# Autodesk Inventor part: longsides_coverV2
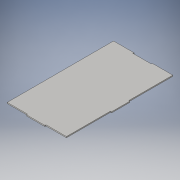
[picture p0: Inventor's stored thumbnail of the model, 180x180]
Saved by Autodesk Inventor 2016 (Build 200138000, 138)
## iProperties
Created: 2015-11
Part Number: longsides_coverV2
Material: Generic
Document SubType Name: Modeling
Designer: silverd
Density: 1 g/cm^3
Appearance: Default
Author: silverd
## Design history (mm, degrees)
sketch "Sketch2"
  geometry: L1 (0, 0)-(56.604, 0); L2 (164.008, 0)-(164.008, -294.694); L3 (164.008, -294.694)-(107.404, -294.694); L4 (0, -294.694)-(0, -172.747); L5 (56.604, 3)-(107.404, 3); L6 (107.404, 3)-(107.404, 0); L7 (56.604, 0)-(56.604, 3); L8 (0, -121.947)-(-3, -121.947); L9 (-3, -121.947)-(-3, -172.747); L10 (-3, -172.747)-(0, -172.747); L11 (107.404, 0)-(164.008, 0); L12 (0, -121.947)-(0, 0); L13 (56.604, -294.694)-(0, -294.694); L14 (107.404, -294.694)-(107.213, -294.694); L15 (107.213, -291.694)-(56.794, -291.694); L16 (56.794, -291.694)-(56.794, -294.694); L17 (107.213, -294.694)-(107.213, -291.694); L18 (56.794, -294.694)-(56.604, -294.694); L19 (56.604, -294.694)-(55.441, -294.694); 7 further points
  constraints: 38 end point, 9 parallel, 5 horizontal, 5 perpendicular, 2 point on line
  dimensions: "d0" = 164.0078 distance of L2.end L4.start (= cover_h_nobase); "d1" = 294.6936 distance of L2.start L2.end (= cover_l + acrylic); "d2" = 50.8 distance of L6.end L1.end (= tab_w); "d3" = 3 distance of L5.end L6.end (= acrylic); "d6" = 3 distance of L4.end L9.end (= acrylic); "d7" = 50.8 distance of L9.end L8.end (= tab_w); "d10" = 50.419 distance of L14.end L16.end (= tab_w - t); "d11" = 3 distance of L16.end L15.end (= acrylic)
extrude "Extrusion1" new body sketch "Sketch2" distance "d8" = 3 (= acrylic); taper "d9" = 0 deg
body "Solid1"
other parameters: "cover_l" = 291.6936 [user parameter; used in 1 equation term], "cover_w" = 228.1936 [user parameter], "acrylic" = 3 [user parameter; used in 5 equation terms], "t" = 0.381 [user parameter; used in 1 equation term], "cover_h_nobase" = 164.0078 [user parameter; used in 1 equation term], "tab_w" = 50.8 [user parameter; used in 3 equation terms]
